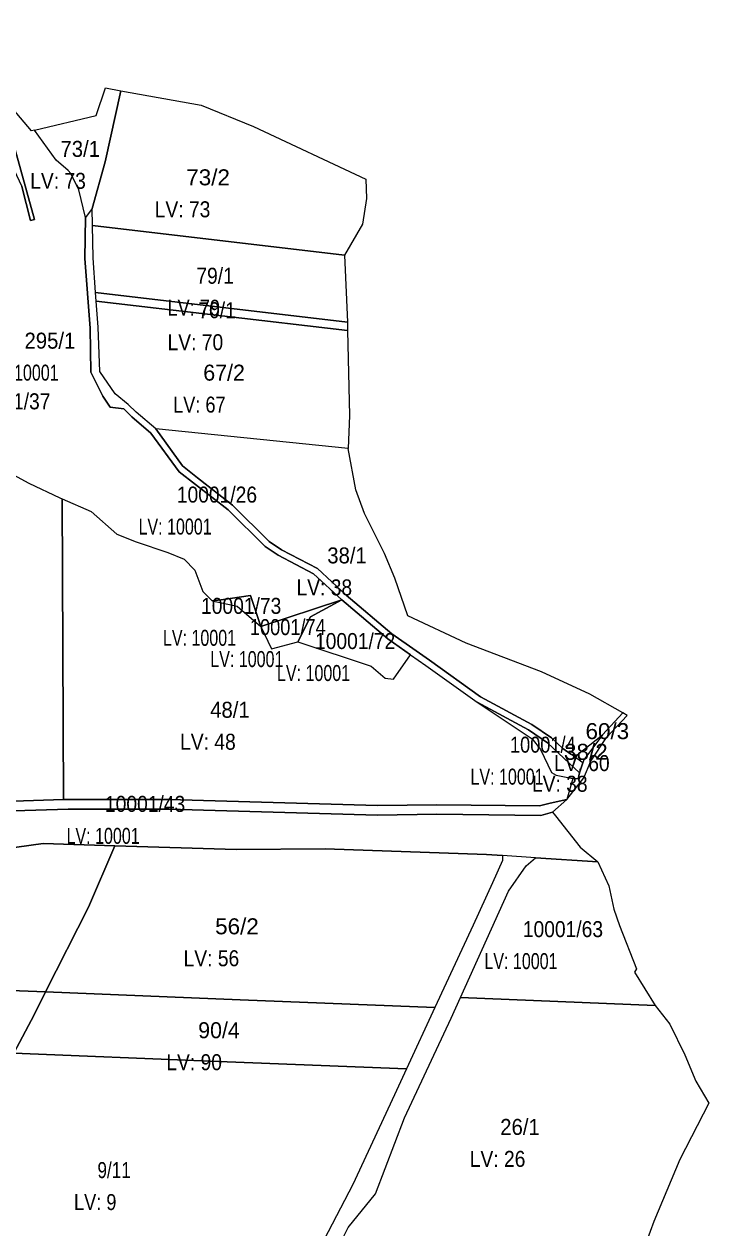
# Model space of a CAD drawing. Extents: x -713758 to -711119, y -1123067 to -1120789.
# Drawn here: x -711548 to -711119, y -1121714 to -1120961 of the extents above; entities that cross this region are included whole.
import ezdxf
from ezdxf.enums import TextEntityAlignment as Align

# ---------------------------------------------------------------- set-up
doc = ezdxf.new("R2010")
doc.units = 0
doc.header["$LTSCALE"] = 4
doc.layers.add('10', color=7, linetype='Continuous', lineweight=13)
doc.layers.add('11', color=7, linetype='Continuous')
doc.layers.add('13', color=7, linetype='Continuous')

msp = doc.modelspace()

# ---------------------------------------------------------------- linework, layer by layer
at = {"layer": '10'}
for points in [[(-711619.36, -1120968.62), (-711610.83, -1120972.06), (-711599.45, -1120984.79), (-711600.05, -1120990.23), (-711591.24, -1120995.77), (-711589, -1121002.29), (-711590.08, -1121009.55), (-711583.73, -1121018.59), (-711572.73, -1121027.16), (-711557.14, -1121045.46), (-711549.04, -1121062.79), (-711543.7, -1121084.05), (-711541.18, -1121083.42), (-711554.41, -1121035.4), (-711561.01, -1121022.81), (-711571.36, -1121012.06), (-711580.21, -1120995.57), (-711585.58, -1120990.25), (-711595.49, -1120968.21), (-711599.93, -1120961.23)], [(-711541.11, -1121027.51), (-711502.56, -1121018.52), (-711496.7, -1121001.17), (-711487.08, -1121002.89), (-711496.94, -1121047.36), (-711505.07, -1121076.63), (-711509.29, -1121082.3), (-711513.46, -1121065), (-711518.46, -1121054.79), (-711520.06, -1121052.78), (-711527.49, -1121046.34)], [(-711505.07, -1121076.63), (-711496.94, -1121047.36), (-711487.08, -1121002.89), (-711436.77, -1121011.86), (-711404.19, -1121025.22), (-711333.86, -1121058.29), (-711333.47, -1121070.32), (-711336.04, -1121086.33), (-711347.18, -1121105.88), (-711504.88, -1121087.29)], [(-711509.6, -1121107.92), (-711506.32, -1121151.44), (-711505.79, -1121179), (-711498.33, -1121194.1), (-711493.7, -1121200.8), (-711485.26, -1121202.02), (-711480.22, -1121206.96), (-711468.28, -1121217.24), (-711450.58, -1121241.43), (-711420, -1121265.11), (-711396.79, -1121287.99), (-711388.65, -1121293.54), (-711366.51, -1121305.09), (-711348.81, -1121321.39), (-711320.06, -1121345.89), (-711305.86, -1121355.8), (-711296.26, -1121362.51), (-711264.27, -1121385.47), (-711232.09, -1121402.73), (-711220.33, -1121410.86), (-711213.34, -1121417.38), (-711200.23, -1121429.63), (-711198.15, -1121423.46), (-711205.73, -1121417.98), (-711210.61, -1121414.46), (-711217.82, -1121407.74), (-711230, -1121399.31), (-711262.15, -1121382.07), (-711293.98, -1121359.22), (-711302.48, -1121353.28), (-711317.62, -1121342.72), (-711346.15, -1121318.41), (-711364.19, -1121301.79), (-711386.59, -1121290.1), (-711394.24, -1121284.89), (-711417.36, -1121262.09), (-711439.22, -1121245.17), (-711448.46, -1121237.55), (-711465.32, -1121214.51), (-711477.51, -1121204.02), (-711482.46, -1121199.16), (-711490.62, -1121192.46), (-711500.31, -1121178.57), (-711501.35, -1121150.78), (-711502.55, -1121134.47), (-711502.94, -1121129.11), (-711504.53, -1121107.56), (-711504.88, -1121087.29), (-711505.07, -1121076.63), (-711509.29, -1121082.3)], [(-711504.88, -1121087.29), (-711347.18, -1121105.88), (-711345.4, -1121147.68), (-711502.94, -1121129.11), (-711504.53, -1121107.56)], [(-711502.94, -1121129.11), (-711345.4, -1121147.68), (-711345.29, -1121153.01), (-711502.55, -1121134.47)], [(-711502.55, -1121134.47), (-711345.29, -1121153.01), (-711344.14, -1121206.01), (-711344.86, -1121226.71), (-711465.32, -1121214.51), (-711477.51, -1121204.02), (-711482.46, -1121199.16), (-711490.62, -1121192.46), (-711500.31, -1121178.57), (-711501.35, -1121150.78)], [(-711465.32, -1121214.51), (-711448.46, -1121237.55), (-711439.22, -1121245.17), (-711417.36, -1121262.09), (-711394.24, -1121284.89), (-711386.59, -1121290.1), (-711364.19, -1121301.79), (-711346.15, -1121318.41), (-711317.62, -1121342.72), (-711302.48, -1121353.28), (-711293.98, -1121359.22), (-711262.15, -1121382.07), (-711230, -1121399.31), (-711217.82, -1121407.74), (-711210.61, -1121414.46), (-711205.73, -1121417.98), (-711201.74, -1121418.3), (-711185.88, -1121405.83), (-711173.17, -1121392.17), (-711193.86, -1121380.4), (-711223.92, -1121366.54), (-711271.07, -1121348.55), (-711307.59, -1121331.52), (-711315.72, -1121307.84), (-711322.13, -1121292.47), (-711334.8, -1121267.35), (-711340.18, -1121252.62), (-711344.86, -1121226.71)], [(-711618.17, -1121253.17), (-711609.76, -1121247.05), (-711603.45, -1121237.97), (-711602.78, -1121237.53), (-711594.67, -1121232.25), (-711577.63, -1121234.79), (-711563.68, -1121238.26), (-711544.69, -1121248.43), (-711525.27, -1121257.57), (-711523.81, -1121258.22), (-711523.01, -1121446.38), (-711554.24, -1121447.4), (-711614.82, -1121453.59), (-711617.32, -1121453.99), (-711617.74, -1121353.58)], [(-711523.81, -1121258.22), (-711505.75, -1121266.2), (-711489.71, -1121280.37), (-711477.51, -1121285.23), (-711457.79, -1121291.77), (-711447.52, -1121296.06), (-711440.76, -1121302.87), (-711435.8, -1121316.3), (-711429.91, -1121322.09), (-711414.32, -1121325.33), (-711399.59, -1121338.19), (-711392.96, -1121351.99), (-711376.5, -1121347.78), (-711330.57, -1121362.89), (-711321.87, -1121370.39), (-711316.47, -1121370.98), (-711305.86, -1121355.8), (-711296.26, -1121362.51), (-711264.27, -1121385.47), (-711229.75, -1121408.27), (-711224.56, -1121414.94), (-711217.66, -1121429.46), (-711214.78, -1121431.09), (-711204.4, -1121433.27), (-711208.14, -1121446.24), (-711218.6, -1121448.55), (-711225.25, -1121450.34), (-711289.45, -1121449.59), (-711326.53, -1121450.1), (-711457.02, -1121446.33), (-711520.24, -1121446.29), (-711523.01, -1121446.38)], [(-711429.91, -1121322.09), (-711414.32, -1121325.33), (-711399.59, -1121338.19), (-711406, -1121318.79), (-711424.42, -1121321.33)], [(-711399.59, -1121338.19), (-711392.96, -1121351.99), (-711376.5, -1121347.78), (-711368.49, -1121332.12), (-711348.81, -1121321.39)], [(-711376.5, -1121347.78), (-711330.57, -1121362.89), (-711321.87, -1121370.39), (-711316.47, -1121370.98), (-711305.86, -1121355.8), (-711320.06, -1121345.89), (-711348.81, -1121321.39), (-711368.49, -1121332.12)], [(-711264.27, -1121385.47), (-711229.75, -1121408.27), (-711224.56, -1121414.94), (-711217.66, -1121429.46), (-711214.78, -1121431.09), (-711204.4, -1121433.27), (-711201.14, -1121433.41), (-711200.23, -1121429.63), (-711213.34, -1121417.38), (-711220.33, -1121410.86), (-711232.09, -1121402.73)], [(-711208.14, -1121446.24), (-711197.53, -1121432.85), (-711193.14, -1121422.42), (-711183.35, -1121407.59), (-711170.34, -1121393.78), (-711173.17, -1121392.17), (-711185.88, -1121405.83), (-711197.46, -1121421.4), (-711198.15, -1121423.46), (-711200.23, -1121429.63), (-711201.14, -1121433.41), (-711204.4, -1121433.27)], [(-711205.73, -1121417.98), (-711201.74, -1121418.3), (-711185.88, -1121405.83), (-711197.46, -1121421.4), (-711198.15, -1121423.46)], [(-711739.48, -1121558.47), (-711726.6, -1121542.17), (-711692.52, -1121502.18), (-711636.21, -1121487.78), (-711535.72, -1121473.88), (-711490.84, -1121475.25), (-711507.4, -1121513.57), (-711534.18, -1121566.68), (-711636.83, -1121562.58)], [(-711534.18, -1121566.68), (-711507.4, -1121513.57), (-711490.84, -1121475.25), (-711414.88, -1121477.57), (-711359.32, -1121477.16), (-711258.32, -1121480.66), (-711248.34, -1121481.33), (-711248.31, -1121484.54), (-711254.56, -1121498.54), (-711266.72, -1121524.9), (-711290.62, -1121576.42), (-711412.4, -1121571.55)], [(-711274.65, -1121570.23), (-711244.68, -1121503.64), (-711233.52, -1121487.73), (-711227.85, -1121482.72), (-711188.75, -1121485.35), (-711181.91, -1121500.25), (-711178.81, -1121514.86), (-711175.23, -1121525.22), (-711164.59, -1121552.35), (-711165.83, -1121554.24), (-711152.83, -1121575.14)], [(-711783.2, -1121595.79), (-711779.66, -1121587.75), (-711755.26, -1121578.43), (-711739.48, -1121558.47), (-711636.83, -1121562.58), (-711534.18, -1121566.68), (-711541.43, -1121581.06), (-711553.99, -1121604.99), (-711668.6, -1121600.39)], [(-711553.99, -1121604.99), (-711541.43, -1121581.06), (-711534.18, -1121566.68), (-711412.4, -1121571.55), (-711290.62, -1121576.42), (-711308.45, -1121614.84), (-711431.22, -1121609.91)], [(-711348.65, -1121721.62), (-711344.84, -1121714.14), (-711327.93, -1121693.04), (-711309.78, -1121645.54), (-711280.48, -1121583.19), (-711274.65, -1121570.23), (-711152.83, -1121575.14), (-711143.77, -1121586.94), (-711134.29, -1121605.95), (-711127.43, -1121622.47), (-711119.27, -1121636.2), (-711137.38, -1121671.56), (-711153.77, -1121710.26), (-711160.57, -1121729.14)], [(-711646.68, -1121735.31), (-711643.78, -1121731.83), (-711619.93, -1121703.21), (-711610.76, -1121707.68), (-711593.45, -1121681.64), (-711562.27, -1121620.75), (-711553.99, -1121604.99), (-711431.22, -1121609.91), (-711308.45, -1121614.84), (-711315.94, -1121630.99), (-711342.08, -1121687.09), (-711372.92, -1121746.38), (-711509.8, -1121740.84)]]:
    msp.add_lwpolyline(points, close=True, dxfattribs=at)
for points in [[(-711563.68, -1121238.26), (-711544.69, -1121248.43), (-711525.27, -1121257.57), (-711523.81, -1121258.22), (-711505.75, -1121266.2), (-711489.71, -1121280.37), (-711477.51, -1121285.23), (-711457.79, -1121291.77), (-711447.52, -1121296.06), (-711440.76, -1121302.87), (-711435.8, -1121316.3), (-711429.91, -1121322.09), (-711424.42, -1121321.33), (-711406, -1121318.79), (-711399.59, -1121338.19), (-711348.81, -1121321.39), (-711366.51, -1121305.09), (-711388.65, -1121293.54), (-711396.79, -1121287.99), (-711420, -1121265.11), (-711450.58, -1121241.43), (-711468.28, -1121217.24), (-711480.22, -1121206.96), (-711485.26, -1121202.02), (-711493.7, -1121200.8), (-711498.33, -1121194.1), (-711505.79, -1121179), (-711506.32, -1121151.44), (-711509.6, -1121107.92), (-711509.29, -1121082.3), (-711513.46, -1121065), (-711518.46, -1121054.79), (-711520.06, -1121052.78), (-711527.49, -1121046.34), (-711541.11, -1121027.51), (-711543.02, -1121027.95), (-711564.93, -1121002.34)], [(-711554.41, -1121035.4), (-711541.18, -1121083.42), (-711543.7, -1121084.05), (-711549.04, -1121062.79)], [(-711554.24, -1121447.4), (-711523.01, -1121446.38), (-711520.24, -1121446.29), (-711457.02, -1121446.33), (-711326.53, -1121450.1), (-711289.45, -1121449.59), (-711225.25, -1121450.34), (-711218.6, -1121448.55), (-711208.14, -1121446.24), (-711217.04, -1121454.34), (-711224.49, -1121456.35), (-711289.48, -1121455.59), (-711326.57, -1121456.1), (-711457.09, -1121452.33), (-711520.14, -1121452.29), (-711553.84, -1121453.39)], [(-711553.84, -1121453.39), (-711520.14, -1121452.29), (-711457.09, -1121452.33), (-711326.57, -1121456.1), (-711289.48, -1121455.59), (-711224.49, -1121456.35), (-711217.04, -1121454.34), (-711215.27, -1121456.59), (-711199.89, -1121476.16), (-711188.75, -1121485.35), (-711227.85, -1121482.72), (-711248.34, -1121481.33), (-711258.32, -1121480.66), (-711359.32, -1121477.16), (-711414.88, -1121477.57), (-711490.84, -1121475.25), (-711535.72, -1121473.88), (-711636.21, -1121487.78)], [(-711348.65, -1121721.62), (-711344.84, -1121714.14), (-711327.93, -1121693.04), (-711309.78, -1121645.54), (-711280.48, -1121583.19), (-711274.65, -1121570.23), (-711244.68, -1121503.64), (-711233.52, -1121487.73), (-711227.85, -1121482.72), (-711248.34, -1121481.33), (-711248.31, -1121484.54), (-711254.56, -1121498.54), (-711266.72, -1121524.9), (-711290.62, -1121576.42), (-711308.45, -1121614.84), (-711315.94, -1121630.99), (-711342.08, -1121687.09), (-711372.92, -1121746.38)]]:
    msp.add_lwpolyline(points, dxfattribs=at)

# ---------------------------------------------------------------- texts
at = {"layer": '11'}
for s, width, p in [('73/1', 0.95, (-711512.52, -1121044.29)), ('73/2', 1.05, (-711432.541, -1121062.1)), ('79/1', 0.9, (-711428.17, -1121123.67)), ('70/1', 0.9, (-711426.921, -1121145.23)), ('295/1', 0.95, (-711531.48, -1121164.28)), ('10001/37', 0.9, (-711556.24, -1121202.23)), ('10001/26', 0.9, (-711427, -1121260.58)), ('38/1', 0.95, (-711345.63, -1121298.62)), ('10001/73', 0.9, (-711411.86, -1121330.18)), ('10001/74', 0.85, (-711382.68, -1121343.46)), ('10001/72', 0.9, (-711340.581, -1121352.19)), ('48/1', 0.95, (-711418.86, -1121395.19)), ('60/3', 1.05, (-711182.81, -1121408.54)), ('10001/4', 0.85, (-711223.171, -1121417.02)), ('38/2', 1.05, (-711196.23, -1121421.49)), ('10001/43', 0.9, (-711471.96, -1121454.06)), ('56/2', 1.05, (-711414.481, -1121530.65)), ('10001/63', 0.9, (-711210.58, -1121532.41)), ('26/1', 0.95, (-711237.44, -1121656.15)), ('9/11', 0.8, (-711491.329, -1121683.15))]:
    msp.add_text(s, height=10, dxfattribs=dict(at, width=width)).set_placement(p, align=Align.CENTER)
for s, p in [('67/2', (-711422.54, -1121184.29)), ('90/4', (-711425.73, -1121595.65))]:
    msp.add_text(s, height=10, dxfattribs=at).set_placement(p, align=Align.CENTER)
at = {"layer": '13'}
for s, width, p in [('LV: 73 ', 0.9, (-711524.733, -1121064.29)), ('LV: 73 ', 0.9, (-711446.862, -1121082.1)), ('LV: 79 ', 0.85, (-711439.949, -1121143.67)), ('LV: 70 ', 0.9, (-711438.832, -1121165.23)), ('LV: 10001 ', 0.75, (-711547.508, -1121184.28)), ('LV: 67 ', 0.85, (-711436.426, -1121204.29)), ('LV: 10001 ', 0.75, (-711451.794, -1121280.58)), ('LV: 38 ', 0.9, (-711358.178, -1121318.62)), ('LV: 10001 ', 0.75, (-711436.52, -1121350.18)), ('LV: 10001 ', 0.75, (-711406.905, -1121363.46)), ('LV: 10001 ', 0.75, (-711365.174, -1121372.19)), ('LV: 48 ', 0.9, (-711430.973, -1121415.19)), ('LV: 60 ', 0.9, (-711197.098, -1121428.54)), ('LV: 10001 ', 0.75, (-711244.15, -1121437.02)), ('LV: 38 ', 0.9, (-711210.886, -1121441.49)), ('LV: 10001 ', 0.75, (-711496.821, -1121474.06)), ('LV: 56 ', 0.9, (-711428.802, -1121550.65)), ('LV: 10001 ', 0.75, (-711235.441, -1121552.41)), ('LV: 90 ', 0.9, (-711439.583, -1121615.65)), ('LV: 26 ', 0.9, (-711249.787, -1121676.15)), ('LV: 9 ', 0.85, (-711501.568, -1121703.15))]:
    msp.add_text(s, height=10, dxfattribs=dict(at, width=width)).set_placement(p, align=Align.CENTER)

doc.saveas('drawing.dxf')
